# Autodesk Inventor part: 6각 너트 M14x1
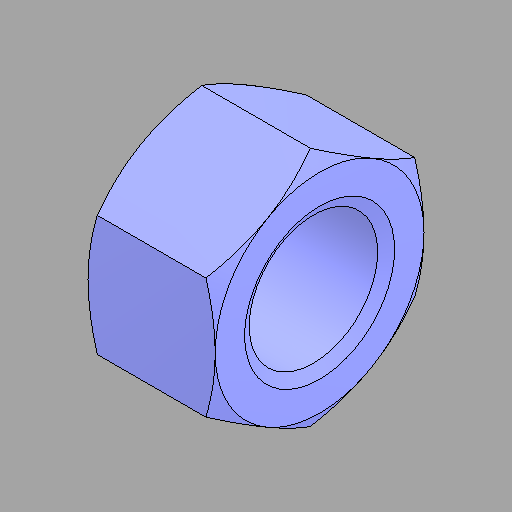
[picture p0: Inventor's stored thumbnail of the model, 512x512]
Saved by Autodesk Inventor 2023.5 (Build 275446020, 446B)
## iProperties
Created: 2025-07
Part Number: 6각 너트 M14x1
Material: 강철, 연강
Description: 6각 너트 및 6각 가는 너트 - 스타일 1
Document SubType Name: Modeling
Designer: 1강의실14
Density: 7.85 g/cm^3
Appearance: 기본값
Author: jhkim
Sending System: Autodesk Inventor 2026
Preprocessor: ST-DEVELOPER v20.1
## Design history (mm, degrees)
feature "Solid1"
node "솔리드1"
